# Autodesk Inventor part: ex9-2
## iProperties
Created: 2006-03
Part Number: ex9-2
Document SubType Name: Sheet Metal
Designer: Elise Moss
Author: Elise Moss
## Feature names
1. Plate1
2. Bend1
3. Cut1
